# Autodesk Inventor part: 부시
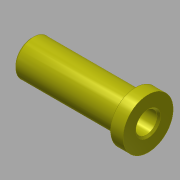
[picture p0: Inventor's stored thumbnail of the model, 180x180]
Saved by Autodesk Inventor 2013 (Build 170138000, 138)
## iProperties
Created: 2016-11
Part Number: 부시
Material: 강철, 연강
Document SubType Name: Modeling
Designer: mduedu
Density: 1 g/cm^3
Author: mduedu
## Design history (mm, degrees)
sketch "스케치1"
  geometry: L1 (0, 0)-(65, 0); L2 (65, 0)-(65, 14); L3 (65, 14)-(58, 14); L4 (58, 14)-(58, 10); L5 (58, 10)-(0, 10); L6 (0, 10)-(0, 0)
  constraints: 12 end point, 3 parallel, 2 perpendicular, 1 horizontal
  dimensions: "d0" = 65 distance of L1.start L1.end; "d1" = 7 distance of L2.end L3.end; "d2" = 28 diameter of L3 L1; "d3" = 20 diameter of L5 L1
revolve "회전1" sketch "스케치1" stored, may be unused: angle "d4" = 90 deg
hole "구멍1" diameter "d7" = 12; stored, may be unused: countersink angle "d11" = 90 deg, drill point angle "d13" = 118 deg; dims "d5" = 10, "d6" = 10, "d8" = 6, "d9" = 4, "d10" = 2, "d12" = 8
chamfer "모따기1" distance "d14" = 1; stored, may be unused: second distance "d15" = 2, angle "d16" = 45 deg
node "솔리드1"
